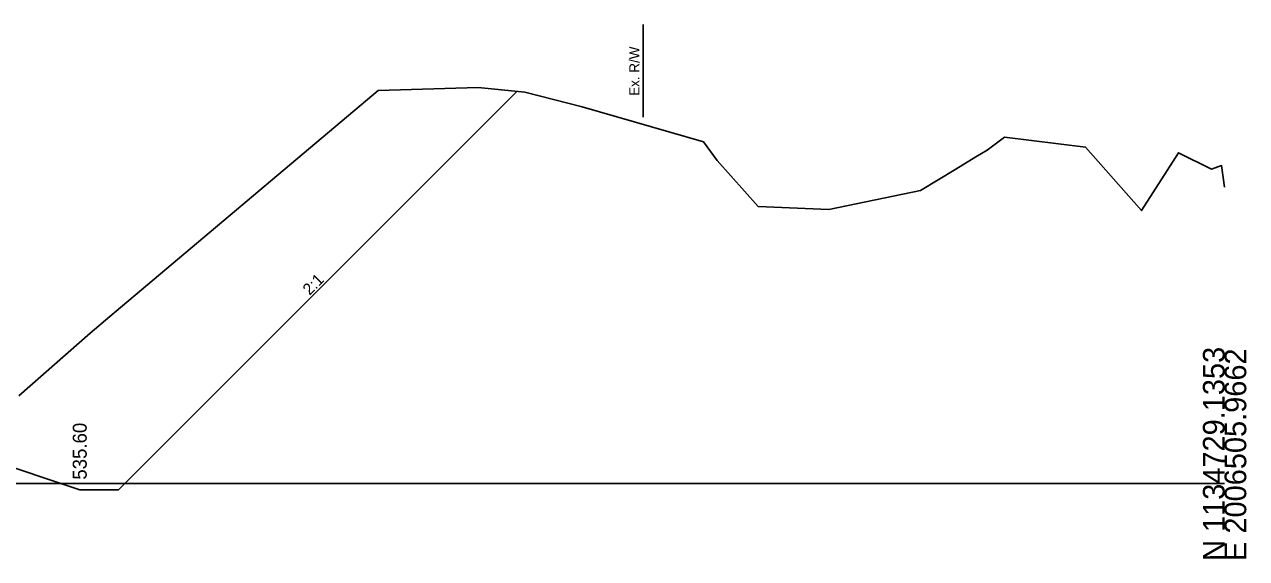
# Model space of a CAD drawing. Extents: x -201 to 2007062, y -213 to 1139737.
# Drawn here: x 1344.9 to 1502.8, y 1490.3 to 1559.4 of the extents above; entities that cross this region are included whole.
import ezdxf

# ---------------------------------------------------------------- set-up
doc = ezdxf.new("R2010")
doc.units = 0
for name, color, linetype in [('RD_GPK_XS_Cell', 7, 'Continuous'), ('RD_Sketch1', 7, 'Continuous'), ('RD_XS_ExGround', 7, 'Continuous'), ('RD_XS_ExRW', 7, 'Continuous'), ('RD_XS_TieSlope', 7, 'Continuous'), ('RD_XS_TX_Ditch', 7, 'Continuous'), ('RD_XS_TX_Slope', 7, 'Continuous')]:
    doc.layers.add(name, color=color, linetype=linetype)

msp = doc.modelspace()

# ---------------------------------------------------------------- linework, layer by layer
at = {"layer": 'RD_GPK_XS_Cell'}
msp.add_line((1250, 1500), (1500, 1500), dxfattribs=at)
at = {"layer": 'RD_XS_ExGround'}
msp.add_lwpolyline([(1344.11, 1511.35), (1353.36, 1519.46), (1355.88, 1521.61), (1390.59, 1550.86), (1403.51, 1551.24), (1409.53, 1550.64), (1416.94, 1548.71), (1432.62, 1544.19), (1434.42, 1541.78), (1439.72, 1535.83), (1448.83, 1535.44), (1460.71, 1537.89), (1465.24, 1540.66), (1467.85, 1542.25), (1469.31, 1543.14), (1471.53, 1544.81), (1482.04, 1543.53), (1489.26, 1535.31), (1494.03, 1542.8), (1498.3, 1540.68), (1499.61, 1541.14), (1500, 1538.33)], dxfattribs=at)
at = {"layer": 'RD_XS_ExRW'}
msp.add_line((1424.85, 1559.39), (1424.85, 1547.39), dxfattribs=at)
at = {"layer": 'RD_XS_TieSlope'}
msp.add_lwpolyline([(1328, 1507.2), (1352, 1499.2), (1357, 1499.2), (1408.54, 1550.74)], dxfattribs=at)

# ---------------------------------------------------------------- texts
at = {"layer": 'RD_GPK_XS_Cell'}
for s, p in [('N 1134729.1353', (1500, 1490)), ('E 2006505.9662', (1502.8, 1490))]:
    msp.add_text(s, height=2.8, rotation=90, dxfattribs=at).set_placement(p)
at = {"layer": 'RD_Sketch1'}
for s, p in [('Exterior Boundary', (1407.98, 1550.69)), ('LOC_C', (1408.31, 1550.69)), ('Cut_Ditch', (1351.7, 1499.15)), ('Cut_Ditch1', (1356.67, 1499.15))]:
    msp.add_text(s, height=0.05, dxfattribs=at).set_placement(p)
at = {"layer": 'RD_XS_ExRW'}
msp.add_text('Ex. R/W ', height=1.3, rotation=90, dxfattribs=at).set_placement((1424.35, 1550.15))
at = {"layer": 'RD_XS_TX_Ditch'}
msp.add_text('535.60', height=1.8, rotation=90, dxfattribs=at).set_placement((1352.9, 1500.51))
at = {"layer": 'RD_XS_TX_Slope'}
msp.add_text('2:1', height=1.5, rotation=45, dxfattribs=at).set_placement((1381.72, 1524.27))

doc.saveas('drawing.dxf')
